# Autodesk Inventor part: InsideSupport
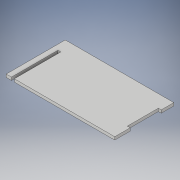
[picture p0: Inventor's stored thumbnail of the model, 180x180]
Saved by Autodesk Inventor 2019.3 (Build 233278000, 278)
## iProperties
Created: 2020-02
Part Number: InsideSupport
Material: Generic
Document SubType Name: Modeling
Designer: KrystynWikoff
Density: 1 g/cm^3
Appearance: Default
Author: KrystynWikoff
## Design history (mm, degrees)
sketch "Sketch1"
  geometry: L1 (0, 0)-(88.9, 0); L2 (88.9, 0)-(88.9, -48.438); L3 (88.9, -48.438)-(0, -48.438); L4 (0, -48.438)-(0, 0)
  constraints: 8 end point, 2 parallel, 1 horizontal, 1 perpendicular
  dimensions: "d0" = 88.9 distance of L1.start L1.end; "d1" = 48.4378 distance of L3.end L1.start
extrude "Extrusion1" new body sketch "Sketch1" distance "d2" = 2.3622; taper "d3" = 0 deg
sketch "Sketch2"
  geometry: L1 (-84.582, 0)-(-82.22, 0); L2 (-82.22, 0)-(-82.22, 38.1); L3 (-82.22, 38.1)-(-84.582, 38.1); L4 (-84.582, 38.1)-(-84.582, 0); L5 (0, 0)-(0, 48.438) reference; L6 (-88.9, 0)-(0, 0) reference; L7 (0, 12.7)-(-2.362, 12.7); L8 (-2.362, 12.7)-(-2.362, 38.1); L9 (-2.362, 38.1)-(0, 38.1); L10 (0, 38.1)-(0, 12.7); L11 (0, 48.438)-(-88.9, 48.438) reference
  constraints: 16 end point, 4 parallel, 2 horizontal, 2 perpendicular, 1 point on line
  dimensions: "d4" = 84.582 distance between parallel lines of L5 L4; "d5" = 2.3622 distance of L2.end L3.end; "d6" = 38.1 distance of L1.end L2.end; "d7" = 0 distance between parallel lines of L6 L1; "d8" = 12.7 distance between parallel lines of L7 L6; "d9" = 10.3378 distance between parallel lines of L11 L9; "d10" = 2.3622 distance of L8.end L9.end
extrude "Extrusion2" cut sketch "Sketch2" distance "d11" = 2.3622; taper "d12" = 0 deg
body "Solid1"
